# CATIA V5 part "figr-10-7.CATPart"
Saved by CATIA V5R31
Part number: Part1
Bounding box of the stored display mesh (mm): x -9.616 to 10, y -9.533 to 9.835, z 0 to 10
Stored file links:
  D:\PROJECTS\Project 2021\US EDITION\CATIA V5 6R 2021\Resources\Part Files\c10_catia_v5_6r2021_prt\c10_catia_v5_6r2021_prt\figr-10-7.CATPart
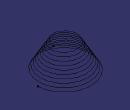
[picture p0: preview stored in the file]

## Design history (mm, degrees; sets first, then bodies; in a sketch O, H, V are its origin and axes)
Set1
  Helix1: Direction {line stored without definition}, RefPoint {point type Coord, X 10, Y 0, Z 0}, Pitch 1, Height 10, TaperAngle 30
Body1 (main body)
